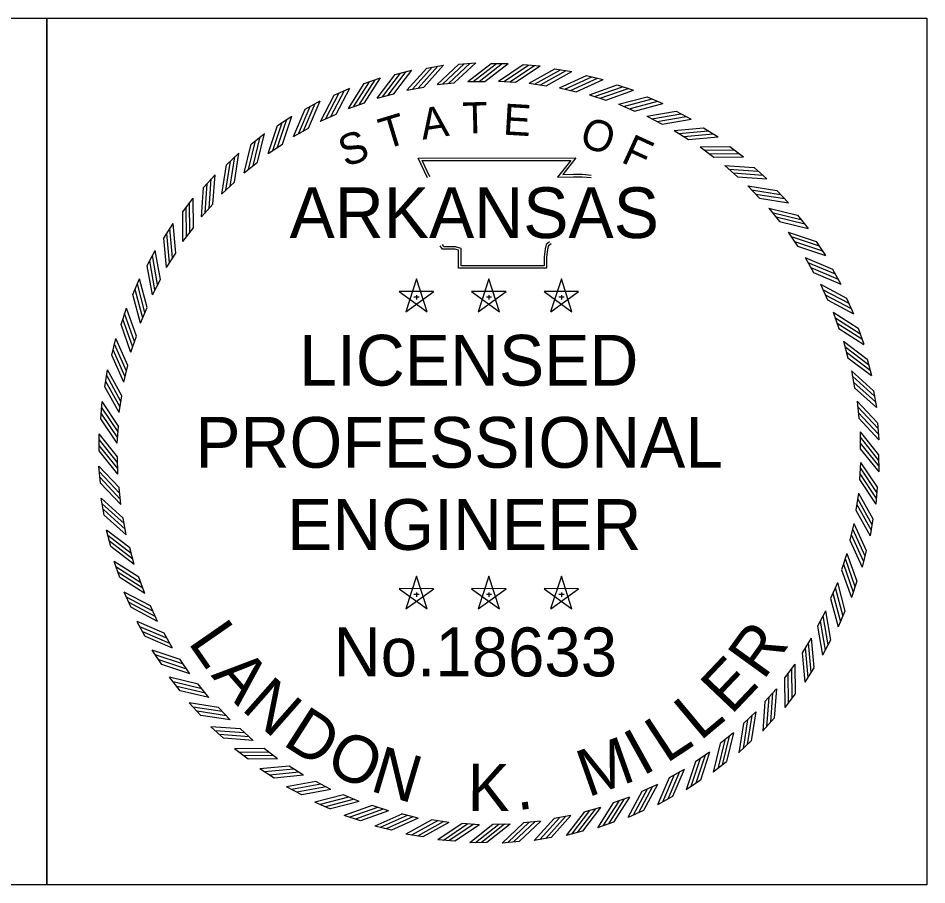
# Model space of a CAD drawing. Extents: x -984 to 3998, y 83 to 2143.
# Drawn here: x 3001.2 to 3290.6, y 212.7 to 488.7 of the extents above; entities that cross this region are included whole.
import ezdxf

# ---------------------------------------------------------------- set-up
doc = ezdxf.new("R2010")
doc.units = 0
doc.layers.add('Level 54', color=7, linetype='Continuous')
doc.layers.add('Level 57', color=7, linetype='Continuous')

msp = doc.modelspace()

# ---------------------------------------------------------------- linework, layer by layer
at = {"layer": 'Level 54'}
for p, q in [((3121.33, 470.71), (3126.59, 472.1)), ((3131.37, 472.76), (3136.73, 473.71)), ((3141.56, 473.98), (3146.98, 474.48)), ((3151.86, 474.28), (3157.3, 474.28)), ((3162.05, 473.88), (3167.47, 473.48)), ((3162.05, 473.88), (3167.48, 473.48)), ((3172.22, 472.56), (3177.6, 471.71)), ((3111.48, 467.83), (3116.61, 469.65)), ((3182.25, 470.4), (3187.54, 469.11)), ((3101.91, 464.16), (3106.87, 466.39)), ((3125.07, 465.77), (3130.44, 466.72)), ((3134.7, 467.53), (3140.13, 468.04)), ((3144.44, 468.5), (3149.89, 468.5)), ((3154.22, 468.65), (3159.66, 468.25)), ((3154.22, 468.65), (3159.66, 468.25)), ((3163.99, 467.99), (3169.37, 467.14)), ((3173.67, 466.53), (3178.96, 465.24)), ((3192.06, 467.42), (3197.23, 465.7)), ((3115.62, 463.22), (3120.89, 464.61)), ((3183.19, 464.28), (3188.36, 462.55)), ((3201.6, 463.65), (3206.6, 461.51)), ((3092.67, 459.7), (3097.43, 462.33)), ((3106.41, 459.9), (3111.55, 461.72)), ((3192.5, 461.24), (3197.51, 459.1)), ((3083.83, 454.49), (3088.36, 457.51)), ((3097.51, 455.83), (3102.48, 458.07)), ((3201.52, 457.45), (3206.34, 454.9)), ((3210.79, 459.1), (3215.6, 456.55)), ((3075.46, 448.58), (3079.72, 451.96)), ((3088.98, 451.04), (3093.75, 453.68)), ((3210.2, 452.93), (3214.79, 449.99)), ((3219.57, 453.8), (3224.15, 450.87)), ((3080.87, 445.56), (3085.4, 448.58)), ((3067.6, 441.99), (3071.57, 445.71)), ((3218.47, 447.7), (3222.81, 444.39)), ((3227.89, 447.8), (3232.21, 444.5)), ((3073.24, 439.43), (3077.51, 442.82)), ((3226.29, 441.81), (3230.34, 438.16)), ((3235.68, 441.13), (3239.72, 437.48)), ((3060.31, 434.77), (3063.96, 438.81)), ((3066.14, 432.69), (3070.12, 436.42)), ((3233.59, 435.3), (3237.32, 431.32)), ((3053.64, 426.98), (3056.94, 431.31)), ((3242.9, 433.84), (3246.62, 429.87)), ((3059.63, 425.38), (3063.28, 429.43)), ((3240.33, 428.2), (3243.72, 423.93)), ((3249.48, 425.98), (3252.87, 421.72)), ((3047.64, 418.66), (3050.57, 423.25)), ((3053.74, 417.57), (3057.04, 421.9)), ((3246.47, 420.57), (3249.49, 416.03)), ((3255.4, 417.6), (3258.42, 413.08)), ((3042.34, 409.88), (3044.89, 414.69)), ((3048.51, 409.29), (3051.45, 413.88)), ((3251.95, 412.46), (3254.59, 407.69)), ((3260.61, 408.77), (3263.24, 404.01)), ((3037.79, 400.69), (3039.93, 405.69)), ((3043.99, 400.61), (3046.54, 405.43)), ((3128.08, 405.64), (3124.68, 395.19)), ((3131.48, 395.2), (3128.09, 405.65)), ((3151.16, 405.64), (3147.76, 395.19)), ((3154.55, 395.2), (3151.17, 405.65)), ((3174.24, 405.64), (3170.84, 395.19)), ((3177.63, 395.2), (3174.25, 405.65)), ((3256.74, 403.93), (3258.97, 398.95)), ((3133.57, 401.65), (3122.59, 401.66)), ((3122.6, 401.65), (3131.48, 395.19)), ((3124.69, 395.2), (3133.59, 401.65)), ((3127.3, 399.9), (3128.94, 399.9)), ((3128.1, 400.48), (3128.1, 399.1)), ((3156.65, 401.65), (3145.67, 401.66)), ((3145.68, 401.65), (3154.56, 395.19)), ((3147.77, 395.2), (3156.66, 401.65)), ((3150.38, 399.9), (3152.01, 399.9)), ((3151.17, 400.48), (3151.17, 399.1)), ((3179.73, 401.65), (3168.74, 401.66)), ((3168.75, 401.65), (3177.63, 395.19)), ((3170.85, 395.2), (3179.74, 401.65)), ((3173.46, 399.9), (3175.09, 399.9)), ((3174.25, 400.48), (3174.25, 399.1)), ((3265.06, 399.53), (3267.29, 394.57)), ((3040.2, 391.59), (3042.34, 396.6)), ((3034.02, 391.16), (3035.73, 396.32)), ((3260.81, 395.03), (3262.63, 389.89)), ((3268.74, 389.96), (3270.56, 384.83)), ((3031.04, 381.34), (3032.33, 386.63)), ((3037.16, 382.28), (3038.89, 387.46)), ((3264.13, 385.82), (3265.52, 380.55)), ((3271.62, 380.11), (3273, 374.85)), ((3028.88, 371.31), (3029.73, 376.69)), ((3034.91, 372.76), (3036.2, 378.06)), ((3266.68, 376.37), (3267.63, 371)), ((3033.45, 363.08), (3034.3, 368.47)), ((3273.67, 370.06), (3274.62, 364.71)), ((3027.56, 361.14), (3027.96, 366.57)), ((3268.44, 366.74), (3268.94, 361.31)), ((3274.89, 359.88), (3275.39, 354.46)), ((3027.09, 350.9), (3027.04, 356.34)), ((3032.79, 353.31), (3033.19, 358.75)), ((3269.4, 357), (3269.45, 351.55)), ((3032.94, 343.53), (3032.89, 348.98)), ((3275.26, 349.63), (3275.31, 344.19)), ((3027.46, 340.65), (3026.96, 346.07)), ((3269.56, 347.22), (3269.16, 341.78)), ((3033.9, 333.79), (3033.4, 339.22)), ((3274.78, 339.39), (3274.39, 333.96)), ((3028.67, 330.47), (3027.73, 335.82)), ((3268.9, 337.45), (3268.05, 332.06)), ((3035.67, 324.16), (3034.72, 329.53)), ((3267.44, 327.77), (3266.15, 322.47)), ((3273.46, 329.22), (3272.62, 323.84)), ((3030.73, 320.42), (3029.34, 325.68)), ((3038.22, 314.71), (3036.83, 319.98)), ((3271.31, 319.19), (3270.02, 313.9)), ((3033.6, 310.57), (3031.79, 315.7)), ((3265.18, 318.25), (3263.46, 313.08)), ((3041.54, 305.5), (3039.72, 310.64)), ((3128.08, 311.01), (3124.68, 300.57)), ((3131.48, 300.58), (3128.09, 311.03)), ((3151.16, 311.01), (3147.76, 300.57)), ((3154.55, 300.58), (3151.17, 311.03)), ((3174.24, 311.01), (3170.84, 300.57)), ((3177.63, 300.58), (3174.25, 311.03)), ((3133.57, 307.03), (3122.59, 307.04)), ((3122.6, 307.03), (3131.48, 300.56)), ((3124.69, 300.58), (3133.59, 307.02)), ((3156.65, 307.03), (3145.67, 307.04)), ((3145.68, 307.03), (3154.56, 300.56)), ((3147.77, 300.58), (3156.66, 307.02)), ((3179.73, 307.03), (3168.74, 307.04)), ((3168.75, 307.03), (3177.63, 300.56)), ((3170.85, 300.58), (3179.74, 307.02)), ((3262.15, 308.94), (3260.01, 303.93)), ((3268.33, 309.38), (3266.61, 304.21)), ((3037.28, 301), (3035.05, 305.96)), ((3127.3, 305.27), (3128.94, 305.27)), ((3128.1, 305.86), (3128.1, 304.48)), ((3150.38, 305.27), (3152.01, 305.27)), ((3151.17, 305.86), (3151.17, 304.48)), ((3173.46, 305.27), (3175.09, 305.27)), ((3174.25, 305.86), (3174.25, 304.48)), ((3045.61, 296.6), (3043.37, 301.58)), ((3258.36, 299.92), (3255.81, 295.1)), ((3264.55, 299.84), (3262.42, 294.84)), ((3041.74, 291.76), (3039.11, 296.52)), ((3050.4, 288.07), (3047.76, 292.84)), ((3253.84, 291.24), (3250.9, 286.65)), ((3260, 290.65), (3257.46, 285.84)), ((3046.95, 282.93), (3043.93, 287.45)), ((3055.88, 279.96), (3052.86, 284.5)), ((3248.61, 282.96), (3245.3, 278.63)), ((3254.71, 281.87), (3251.77, 277.28)), ((3052.86, 274.55), (3049.48, 278.81)), ((3062.01, 272.33), (3058.62, 276.6)), ((3242.72, 275.15), (3239.06, 271.1)), ((3248.71, 273.55), (3245.4, 269.23)), ((3059.45, 266.69), (3055.73, 270.66)), ((3068.75, 265.23), (3065.02, 269.21)), ((3236.21, 267.84), (3232.23, 264.11)), ((3242.04, 265.76), (3238.39, 261.72)), ((3066.67, 259.4), (3062.63, 263.05)), ((3076.06, 258.72), (3072.01, 262.37)), ((3229.11, 261.1), (3224.84, 257.72)), ((3234.75, 258.54), (3230.78, 254.82)), ((3074.46, 252.73), (3070.13, 256.03)), ((3083.87, 252.83), (3079.54, 256.14)), ((3221.48, 254.97), (3216.94, 251.95)), ((3226.89, 251.95), (3222.63, 248.57)), ((3082.77, 246.73), (3078.19, 249.66)), ((3092.15, 247.6), (3087.56, 250.54)), ((3213.37, 249.49), (3208.6, 246.85)), ((3218.51, 246.04), (3213.99, 243.02)), ((3091.56, 241.44), (3086.75, 243.98)), ((3100.83, 243.08), (3096.01, 245.63)), ((3204.84, 244.7), (3199.86, 242.46)), ((3109.85, 239.29), (3104.84, 241.43)), ((3195.94, 240.63), (3190.79, 238.81)), ((3209.68, 240.83), (3204.91, 238.2)), ((3100.75, 236.88), (3095.75, 239.02)), ((3119.16, 236.25), (3113.98, 237.98)), ((3110.28, 233.11), (3105.12, 234.83)), ((3128.68, 234), (3123.38, 235.29)), ((3177.28, 234.76), (3171.91, 233.81)), ((3186.73, 237.31), (3181.45, 235.92)), ((3200.44, 236.38), (3195.48, 234.14)), ((3138.36, 232.54), (3132.97, 233.39)), ((3148.12, 231.88), (3142.69, 232.28)), ((3157.91, 232.04), (3152.46, 231.99)), ((3167.65, 233), (3162.22, 232.5)), ((3190.87, 232.7), (3185.74, 230.88)), ((3120.1, 230.13), (3114.81, 231.42)), ((3130.12, 227.97), (3124.75, 228.82)), ((3181.02, 229.82), (3175.76, 228.44)), ((3140.3, 226.65), (3134.87, 227.05)), ((3150.54, 226.18), (3145.1, 226.13)), ((3160.79, 226.55), (3155.37, 226.05)), ((3170.97, 227.77), (3165.61, 226.82))]:
    msp.add_line(p, q, dxfattribs=at)
for points in [[(3120.88, 464.61), (3126.59, 472.1)], [(3125.06, 465.77), (3131.37, 472.76)], [(3126.79, 466.06), (3133.09, 473.05)], [(3128.64, 466.42), (3134.95, 473.42)], [(3130.43, 466.72), (3136.74, 473.71)], [(3134.69, 467.53), (3141.55, 473.98)], [(3136.43, 467.67), (3143.3, 474.12)], [(3138.31, 467.89), (3145.17, 474.33)], [(3140.12, 468.04), (3146.98, 474.48)], [(3144.43, 468.49), (3151.85, 474.28)], [(3146.18, 468.47), (3153.6, 474.26)], [(3148.07, 468.52), (3155.49, 474.31)], [(3149.88, 468.5), (3157.31, 474.29)], [(3154.21, 468.64), (3162.04, 473.87)], [(3154.21, 468.64), (3162.04, 473.87)], [(3155.96, 468.5), (3163.79, 473.73)], [(3155.96, 468.5), (3163.79, 473.73)], [(3157.85, 468.4), (3165.67, 473.63)], [(3157.85, 468.4), (3165.68, 473.63)], [(3159.65, 468.25), (3167.48, 473.48)], [(3159.65, 468.25), (3167.48, 473.48)], [(3163.98, 467.99), (3172.21, 472.55)], [(3165.71, 467.7), (3173.94, 472.26)], [(3167.58, 467.45), (3175.81, 472.01)], [(3109.83, 461.13), (3114.9, 469.07)], [(3111.55, 461.72), (3116.61, 469.65)], [(3115.61, 463.22), (3121.32, 470.7)], [(3117.31, 463.65), (3123.02, 471.13)], [(3119.13, 464.17), (3124.83, 471.66)], [(3169.37, 467.15), (3177.6, 471.71)], [(3173.66, 466.53), (3182.24, 470.4)], [(3175.36, 466.1), (3183.94, 469.97)], [(3177.2, 465.69), (3185.78, 469.56)], [(3178.96, 465.25), (3187.54, 469.12)], [(3102.48, 458.07), (3106.87, 466.39)], [(3106.41, 459.89), (3111.48, 467.83)], [(3108.06, 460.46), (3113.13, 468.4)], [(3183.18, 464.27), (3192.05, 467.42)], [(3184.84, 463.71), (3193.71, 466.85)], [(3186.64, 463.15), (3195.52, 466.3)], [(3097.51, 455.82), (3101.9, 464.15)], [(3099.11, 456.53), (3103.51, 464.85)], [(3100.82, 457.34), (3105.21, 465.66)], [(3188.36, 462.56), (3197.23, 465.71)], [(3192.49, 461.24), (3201.59, 463.65)], [(3090.51, 451.86), (3094.21, 460.52)], [(3092.15, 452.82), (3095.84, 461.47)], [(3093.74, 453.68), (3097.43, 462.34)], [(3194.09, 460.54), (3203.19, 462.94)], [(3195.85, 459.83), (3204.95, 462.24)], [(3197.5, 459.11), (3206.61, 461.51)], [(3085.4, 448.58), (3088.36, 457.52)], [(3088.97, 451.03), (3092.67, 459.69)], [(3201.51, 457.45), (3210.78, 459.09)], [(3203.05, 456.62), (3212.32, 458.26)], [(3204.74, 455.77), (3214.01, 457.41)], [(3080.86, 445.55), (3083.83, 454.48)], [(3082.33, 446.51), (3085.3, 455.44)], [(3083.88, 447.59), (3086.85, 456.53)], [(3206.33, 454.91), (3215.6, 456.55)], [(3077.5, 442.81), (3079.72, 451.96)], [(3210.19, 452.93), (3219.56, 453.8)], [(3211.66, 451.97), (3221.03, 452.84)], [(3213.27, 450.99), (3222.64, 451.86)], [(3074.62, 440.49), (3076.84, 449.64)], [(3076.07, 441.7), (3078.29, 450.85)], [(3214.79, 449.99), (3224.16, 450.87)], [(3070.11, 436.42), (3071.57, 445.72)], [(3073.24, 439.42), (3075.45, 448.57)], [(3218.47, 447.7), (3227.88, 447.8)], [(3219.85, 446.63), (3229.26, 446.72)], [(3067.43, 433.86), (3068.88, 443.17)], [(3068.78, 435.19), (3070.23, 444.49)], [(3131.59, 437.87), (3128.69, 444.15), (3178.87, 444.18), (3174.68, 438.91), (3178.08, 438.96), (3180.93, 438.99), (3183.78, 438.68)], [(3132.31, 438.2), (3129.93, 443.36), (3177.22, 443.38), (3173.01, 438.1), (3178.09, 438.16), (3180.89, 438.2), (3183.69, 437.89)], [(3221.38, 445.51), (3230.79, 445.61)], [(3222.81, 444.4), (3232.22, 444.5)], [(3066.14, 432.68), (3067.59, 441.98)], [(3226.28, 441.81), (3235.67, 441.13)], [(3227.57, 440.63), (3236.96, 439.95)], [(3062.05, 428.09), (3062.73, 437.48)], [(3063.27, 429.43), (3063.96, 438.82)], [(3229, 439.39), (3238.39, 438.71)], [(3230.33, 438.16), (3239.72, 437.48)], [(3059.62, 425.37), (3060.31, 434.76)], [(3060.81, 426.66), (3061.49, 436.05)], [(3233.59, 435.3), (3242.89, 433.84)], [(3057.04, 421.9), (3056.94, 431.31)], [(3234.77, 434.01), (3244.07, 432.56)], [(3236.1, 432.66), (3245.4, 431.21)], [(3237.32, 431.33), (3246.62, 429.87)], [(3054.81, 418.94), (3054.71, 428.35)], [(3055.92, 420.47), (3055.83, 429.88)], [(3053.74, 417.56), (3053.64, 426.97)], [(3240.33, 428.2), (3249.48, 425.98)], [(3241.4, 426.82), (3250.55, 424.6)], [(3051.44, 413.88), (3050.57, 423.25)], [(3242.61, 425.37), (3251.76, 423.15)], [(3243.72, 423.94), (3252.87, 421.72)], [(3049.47, 410.75), (3048.6, 420.12)], [(3050.45, 412.36), (3049.58, 421.74)], [(3246.46, 420.57), (3255.39, 417.61)], [(3048.51, 409.28), (3047.64, 418.66)], [(3170.96, 416.84), (3170.11, 416.15), (3169.82, 415.11), (3169.54, 412.5), (3169.54, 409.04), (3141.53, 409.04), (3141.53, 413.72), (3141.53, 414.76), (3140.39, 415.11), (3136.41, 415.11), (3135.7, 416.19)], [(3170.46, 417.46), (3169.41, 416.6), (3169.04, 415.25), (3168.74, 412.55), (3168.74, 409.83), (3142.32, 409.83), (3142.32, 413.72), (3142.32, 415.35), (3140.51, 415.9), (3136.83, 415.9), (3136.36, 416.62)], [(3247.42, 419.11), (3256.35, 416.14)], [(3248.5, 417.56), (3257.43, 414.59)], [(3046.53, 405.43), (3044.89, 414.7)], [(3249.49, 416.04), (3258.42, 413.08)], [(3044.82, 402.14), (3043.18, 411.41)], [(3045.67, 403.83), (3044.02, 413.1)], [(3251.94, 412.47), (3260.6, 408.77)], [(3043.99, 400.6), (3042.34, 409.87)], [(3252.77, 410.93), (3261.43, 407.23)], [(3253.72, 409.29), (3262.38, 405.6)], [(3042.33, 396.6), (3039.93, 405.7)], [(3254.59, 407.7), (3263.25, 404)], [(3040.9, 393.18), (3038.5, 402.29)], [(3041.61, 394.94), (3039.2, 404.04)], [(3256.73, 403.93), (3265.06, 399.54)], [(3257.43, 402.33), (3265.76, 397.93)], [(3040.2, 391.58), (3037.79, 400.68)], [(3258.25, 400.62), (3266.57, 396.23)], [(3258.98, 398.96), (3267.3, 394.57)], [(3038.29, 385.74), (3035.14, 394.61)], [(3038.88, 387.45), (3035.73, 396.32)], [(3260.8, 395.03), (3268.74, 389.96)], [(3037.16, 382.27), (3034.02, 391.15)], [(3037.73, 383.93), (3034.59, 392.8)], [(3261.37, 393.38), (3269.3, 388.31)], [(3262.04, 391.61), (3269.97, 386.54)], [(3262.63, 389.89), (3270.56, 384.82)], [(3036.19, 378.05), (3032.32, 386.63)], [(3264.12, 385.83), (3271.61, 380.12)], [(3035.34, 374.45), (3031.47, 383.03)], [(3035.75, 376.29), (3031.88, 384.88)], [(3264.55, 384.13), (3272.04, 378.42)], [(3265.08, 382.31), (3272.56, 376.6)], [(3034.91, 372.75), (3031.04, 381.33)], [(3265.52, 380.55), (3273.01, 374.85)], [(3034.29, 368.46), (3029.73, 376.69)], [(3266.68, 376.38), (3273.67, 370.07)], [(3033.99, 366.67), (3029.43, 374.91)], [(3266.96, 374.65), (3273.95, 368.34)], [(3033.45, 363.07), (3028.89, 371.31)], [(3033.74, 364.8), (3029.17, 373.03)], [(3267.33, 372.8), (3274.32, 366.49)], [(3267.63, 371.01), (3274.62, 364.7)], [(3033.04, 356.94), (3027.81, 364.77)], [(3033.19, 358.75), (3027.96, 366.57)], [(3268.44, 366.75), (3274.88, 359.89)], [(3268.58, 365), (3275.03, 358.14)], [(3032.94, 355.05), (3027.71, 362.88)], [(3268.8, 363.13), (3275.24, 356.27)], [(3032.8, 353.31), (3027.57, 361.14)], [(3268.95, 361.32), (3275.39, 354.46)], [(3032.89, 348.97), (3027.03, 356.34)], [(3269.4, 357.01), (3275.26, 349.64)], [(3032.89, 347.16), (3027.03, 354.53)], [(3269.4, 355.26), (3275.26, 347.89)], [(3269.46, 353.37), (3275.31, 346)], [(3032.95, 345.27), (3027.09, 352.64)], [(3032.95, 343.52), (3027.09, 350.89)], [(3269.46, 351.56), (3275.31, 344.19)], [(3033.4, 339.21), (3026.95, 346.07)], [(3269.41, 345.48), (3274.64, 337.65)], [(3269.55, 347.22), (3274.78, 339.4)], [(3033.55, 337.4), (3027.1, 344.27)], [(3033.77, 335.53), (3027.32, 342.39)], [(3269.16, 341.78), (3274.39, 333.96)], [(3269.31, 343.59), (3274.54, 335.76)], [(3033.91, 333.78), (3027.46, 340.64)], [(3034.72, 329.52), (3027.72, 335.83)], [(3268.61, 335.73), (3273.17, 327.5)], [(3268.9, 337.46), (3273.46, 329.23)], [(3035.01, 327.74), (3028.02, 334.04)], [(3268.35, 333.86), (3272.92, 325.62)], [(3035.38, 325.88), (3028.39, 332.19)], [(3035.67, 324.15), (3028.68, 330.46)], [(3268.06, 332.07), (3272.62, 323.84)], [(3267.44, 327.78), (3271.3, 319.2)], [(3036.83, 319.98), (3029.34, 325.68)], [(3266.6, 324.24), (3270.47, 315.66)], [(3267.01, 326.08), (3270.88, 317.5)], [(3037.27, 318.22), (3029.78, 323.93)], [(3037.79, 316.4), (3030.3, 322.11)], [(3266.15, 322.48), (3270.02, 313.9)], [(3038.22, 314.71), (3030.73, 320.41)], [(3039.72, 310.64), (3031.78, 315.71)], [(3264.61, 316.6), (3267.76, 307.73)], [(3265.18, 318.26), (3268.33, 309.38)], [(3040.31, 308.92), (3032.37, 313.99)], [(3263.47, 313.08), (3266.61, 304.21)], [(3264.06, 314.79), (3267.2, 305.92)], [(3040.98, 307.16), (3033.04, 312.22)], [(3041.54, 305.5), (3033.61, 310.57)], [(3261.45, 307.35), (3263.85, 298.25)], [(3262.15, 308.95), (3264.55, 299.85)], [(3043.37, 301.57), (3035.05, 305.97)], [(3044.1, 299.91), (3035.77, 304.31)], [(3260.01, 303.93), (3262.42, 294.83)], [(3260.74, 305.59), (3263.14, 296.49)], [(3044.91, 298.2), (3036.59, 302.6)], [(3045.62, 296.6), (3037.29, 301)], [(3257.53, 298.39), (3259.17, 289.12)], [(3258.36, 299.93), (3260, 290.66)], [(3047.76, 292.83), (3039.1, 296.53)], [(3256.68, 296.7), (3258.32, 287.43)], [(3048.62, 291.24), (3039.96, 294.93)], [(3049.57, 289.61), (3040.92, 293.3)], [(3255.82, 295.1), (3257.46, 285.83)], [(3050.41, 288.07), (3041.75, 291.76)], [(3252.88, 289.78), (3253.75, 280.41)], [(3253.84, 291.25), (3254.71, 281.88)], [(3052.86, 284.49), (3043.92, 287.46)], [(3250.9, 286.65), (3251.78, 277.28)], [(3251.89, 288.17), (3252.77, 278.8)], [(3053.85, 282.97), (3044.91, 285.94)], [(3054.93, 281.42), (3046, 284.39)], [(3055.89, 279.96), (3046.95, 282.92)], [(3247.54, 281.59), (3247.63, 272.18)], [(3248.61, 282.97), (3248.71, 273.56)], [(3058.62, 276.6), (3049.47, 278.81)], [(3245.31, 278.63), (3245.4, 269.22)], [(3246.42, 280.06), (3246.52, 270.65)], [(3059.74, 275.16), (3050.59, 277.38)], [(3060.94, 273.71), (3051.8, 275.93)], [(3242.72, 275.16), (3242.04, 265.77)], [(3062.02, 272.33), (3052.87, 274.55)], [(3240.3, 272.44), (3239.62, 263.05)], [(3241.54, 273.87), (3240.85, 264.48)], [(3065.02, 269.2), (3055.72, 270.66)], [(3066.25, 267.87), (3056.95, 269.33)], [(3239.07, 271.1), (3238.39, 261.71)], [(3067.57, 266.52), (3058.27, 267.98)], [(3068.76, 265.23), (3059.46, 266.69)], [(3234.92, 266.67), (3233.46, 257.37)], [(3236.21, 267.85), (3234.75, 258.55)], [(3232.23, 264.12), (3230.78, 254.81)], [(3233.57, 265.34), (3232.11, 256.04)], [(3072.01, 262.37), (3062.62, 263.05)], [(3073.35, 261.14), (3063.96, 261.82)], [(3074.78, 259.9), (3065.39, 260.58)], [(3229.11, 261.11), (3226.89, 251.96)], [(3076.06, 258.72), (3066.67, 259.4)], [(3224.84, 257.72), (3222.63, 248.57)], [(3226.27, 258.83), (3224.06, 249.68)], [(3227.73, 260.04), (3225.51, 250.89)], [(3079.54, 256.13), (3070.13, 256.03)], [(3080.97, 255.02), (3071.56, 254.92)], [(3221.48, 254.98), (3218.52, 246.05)], [(3082.5, 253.9), (3073.09, 253.81)], [(3083.88, 252.83), (3074.47, 252.73)], [(3216.95, 251.95), (3213.98, 243.01)], [(3218.47, 252.94), (3215.5, 244.01)], [(3220.02, 254.02), (3217.05, 245.09)], [(3087.56, 250.54), (3078.19, 249.66)], [(3089.08, 249.54), (3079.7, 248.67)], [(3213.37, 249.5), (3209.68, 240.84)], [(3090.69, 248.56), (3081.32, 247.69)], [(3092.16, 247.6), (3082.78, 246.73)], [(3208.61, 246.85), (3204.91, 238.19)], [(3210.2, 247.72), (3206.51, 239.06)], [(3211.83, 248.67), (3208.14, 240.01)], [(3096.01, 245.62), (3086.74, 243.98)], [(3097.61, 244.76), (3088.34, 243.12)], [(3099.3, 243.91), (3090.03, 242.27)], [(3201.53, 243.19), (3197.13, 234.87)], [(3203.24, 244), (3198.84, 235.68)], [(3204.84, 244.71), (3200.44, 236.38)], [(3100.84, 243.08), (3091.57, 241.44)], [(3104.84, 241.43), (3095.74, 239.02)], [(3106.5, 240.7), (3097.4, 238.29)], [(3195.94, 240.64), (3190.87, 232.7)], [(3199.87, 242.46), (3195.47, 234.14)], [(3108.26, 239.99), (3099.15, 237.59)], [(3109.86, 239.29), (3100.76, 236.89)], [(3113.99, 237.97), (3105.12, 234.82)], [(3115.7, 237.38), (3106.83, 234.24)], [(3186.73, 237.31), (3181.03, 229.83)], [(3190.8, 238.81), (3185.73, 230.88)], [(3192.52, 239.4), (3187.45, 231.47)], [(3194.28, 240.07), (3189.21, 232.13)], [(3117.51, 236.83), (3108.64, 233.68)], [(3119.16, 236.26), (3110.29, 233.11)], [(3123.39, 235.28), (3114.81, 231.42)], [(3125.15, 234.84), (3116.56, 230.97)], [(3126.99, 234.43), (3118.41, 230.56)], [(3175.56, 234.48), (3169.25, 227.48)], [(3177.28, 234.76), (3170.98, 227.77)], [(3181.46, 235.92), (3175.76, 228.43)], [(3183.22, 236.36), (3177.51, 228.88)], [(3185.04, 236.88), (3179.33, 229.4)], [(3128.69, 234), (3120.11, 230.13)], [(3132.98, 233.38), (3124.74, 228.82)], [(3134.77, 233.08), (3126.53, 228.52)], [(3136.64, 232.83), (3128.41, 228.27)], [(3138.37, 232.54), (3130.13, 227.98)], [(3142.69, 232.28), (3134.86, 227.05)], [(3144.5, 232.13), (3136.67, 226.9)], [(3146.39, 232.03), (3138.56, 226.8)], [(3148.13, 231.89), (3140.3, 226.66)], [(3152.46, 231.98), (3145.09, 226.12)], [(3154.28, 231.98), (3146.91, 226.12)], [(3156.17, 232.04), (3148.8, 226.18)], [(3157.92, 232.04), (3150.55, 226.18)], [(3162.23, 232.49), (3155.37, 226.05)], [(3164.03, 232.64), (3157.17, 226.2)], [(3165.91, 232.86), (3159.05, 226.41)], [(3167.66, 233), (3160.8, 226.56)], [(3171.92, 233.81), (3165.61, 226.82)], [(3173.7, 234.11), (3167.4, 227.12)]]:
    msp.add_lwpolyline(points, dxfattribs=at)
at = {"layer": 'Level 57'}
for points in [[(2730.1, 488.67), (3010.37, 488.67), (3010.37, 212.74), (2730.1, 212.74)], [(3010.37, 488.67), (3290.65, 488.67), (3290.65, 212.74), (3010.37, 212.74)]]:
    msp.add_lwpolyline(points, close=True, dxfattribs=at)

# ---------------------------------------------------------------- texts
at = {"layer": 'Level 54'}
for s, height, rotation, p in [('A', 9.9, 8.6788, (3130.06, 449.95)), ('T', 9.9, 1.4789, (3142.84, 451.92)), ('T', 9.9, 1.4789, (3142.84, 451.92)), ('E', 9.9, 356.672, (3155.51, 451.62)), ('T', 9.9, 16.9015, (3118.04, 446.81)), ('O', 9.9, 341.2218, (3179.54, 448.22)), ('S', 9.9, 19.7726, (3105.46, 441.16)), ('F', 9.9, 335.3628, (3192.88, 443.01)), ('L', 15.03, 304.7099, (3055.14, 289.95)), ('R', 15.03, 54.15, (3238.59, 277.6)), ('A', 15.03, 311.2763, (3062.48, 279.34)), ('E', 15.03, 46.4892, (3228.34, 266.59)), ('N', 15.03, 318.5723, (3072, 268.63)), ('L', 15.03, 39.9228, (3218.44, 258.31)), ('D', 15.03, 327.3275, (3085.11, 257.51)), ('L', 15.03, 33.3564, (3207.67, 251.22)), ('O', 15.03, 335.3531, (3098.49, 249.17)), ('I', 15.03, 28.9788, (3200.07, 247.19)), ('M', 15.03, 19.494, (3182.68, 240.53)), ('N', 15.03, 343.3787, (3112.9, 242.78)), ('K', 15.03, 359.7948, (3144.38, 236.26)), ('.', 15.03, 7.8204, (3160.15, 236.41))]:
    msp.add_text(s, height=height, rotation=rotation, dxfattribs=at).set_placement(p)
for s, height, p in [('ARKANSAS', 16.155, (3087.67, 418.65)), ('LICENSED', 16.155, (3090.75, 371.69)), ('PROFESSIONAL', 16.1547, (3057.67, 345.54)), ('ENGINEER', 16.155, (3086.9, 319.38)), ('No.18633', 15.578, (3101.67, 279.1))]:
    msp.add_text(s, height=height, dxfattribs=at).set_placement(p)

doc.saveas('drawing.dxf')
